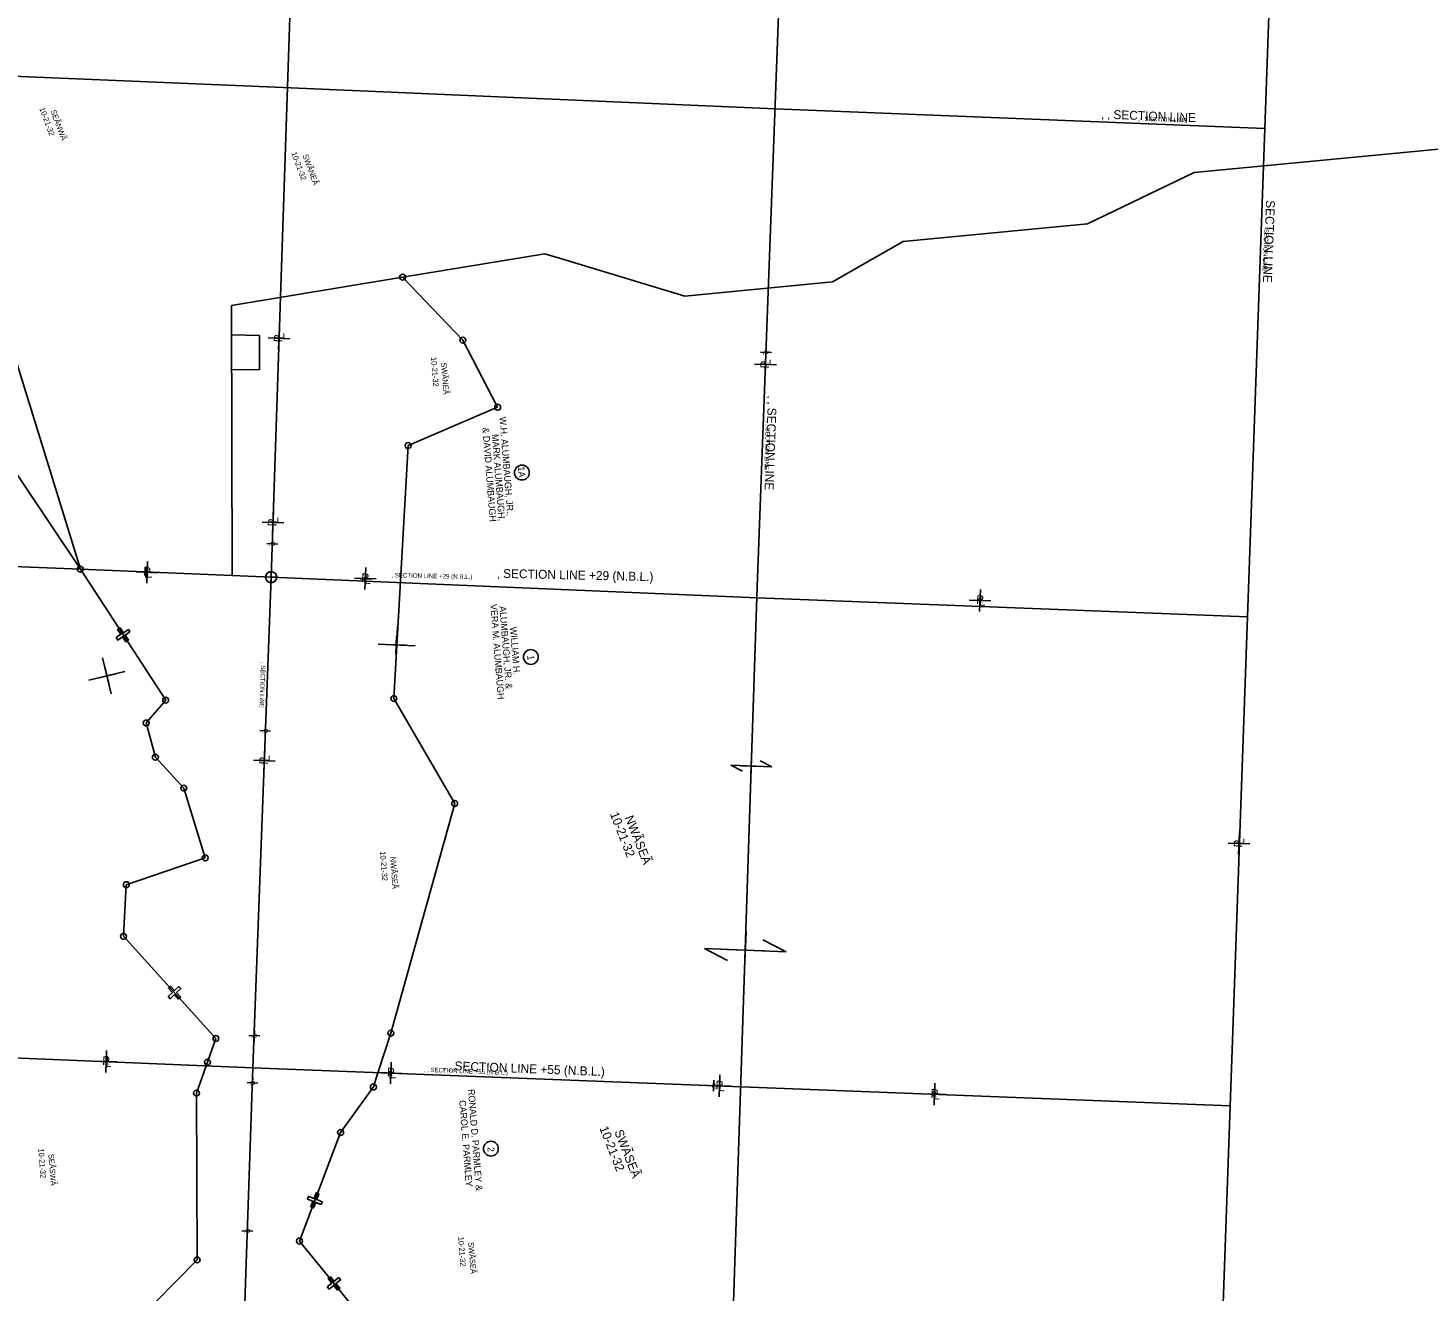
# Model space of a CAD drawing. Extents: x 2814293 to 2835768, y 121185 to 156337.
# Drawn here: x 2823143 to 2826922, y 142244 to 145654 of the extents above; entities that cross this region are included whole.
import ezdxf

# ---------------------------------------------------------------- set-up
doc = ezdxf.new("R2010")
doc.units = 0
for name, color, linetype in [('Default', 7, 'Continuous'), ('Photo-Retaining wall', 7, 'Continuous'), ('Roadway-Alignment notes', 7, 'Continuous'), ('Roadway-Ditches', 7, 'Continuous'), ('Roadway-Edge of pavement', 7, 'Continuous'), ('Roadway-Edge of shoulder', 7, 'Continuous'), ('Roadway-Entrances', 7, 'Continuous'), ('Roadway-New rw', 7, 'Continuous'), ('Roadway-Safety', 7, 'Continuous'), ('Roadway-Walls', 7, 'Continuous'), ('Scratch-2', 7, 'Continuous'), ('Scratch-4', 7, 'Continuous'), ('Scratch-5', 7, 'Continuous'), ('Text-New rw label', 7, 'Continuous'), ('Traffic_Control-Traffic barriers', 7, 'Continuous')]:
    doc.layers.add(name, color=color, linetype=linetype)

msp = doc.modelspace()

# ---------------------------------------------------------------- linework, layer by layer
at = {"layer": 'Default'}
for p, q in [((2824135.8, 143938), (2824140.5, 144037.9)), ((2824136.1, 143963), (2824137.9, 144013)), ((2824188.1, 143985.6), (2824088.2, 143990.3)), ((2824162, 143987.1), (2824112, 143988.9)), ((2823367.6, 143855.9), (2823344, 143953.1)), ((2823404.4, 143916.3), (2823307.2, 143892.7)), ((2823380.1, 143910.4), (2823331.5, 143898.6)), ((2823361.7, 143880.2), (2823349.9, 143928.8))]:
    msp.add_line(p, q, dxfattribs=at)
at = {"layer": 'Roadway-Ditches'}
for centre in [(2824476, 144453.5), (2824500.2, 143955.6), (2824392.4, 142628)]:
    msp.add_circle(centre, 20, dxfattribs=at)
at = {"layer": 'Roadway-Edge of pavement'}
for p, q in [((2825096.2, 143686.1), (2825094.3, 143636.2)), ((2825119.1, 143675), (2825150.2, 143659)), ((2825150.2, 143659), (2825040.3, 143663.3)), ((2825071.4, 143647.3), (2825040.3, 143663.3)), ((2825070.3, 143662.1), (2825120.2, 143660.2)), ((2825095.2, 143661.2), (2825095.2, 143661.2))]:
    msp.add_line(p, q, dxfattribs=at)
at = {"layer": 'Roadway-Edge of shoulder'}
for p, q in [((2823819.2, 144786.5), (2823821.5, 144845.4)), ((2823791, 144817.1), (2823849.8, 144814.8)), ((2825132.4, 144715.7), (2825134.5, 144774.6)), ((2825104, 144746.2), (2825162.9, 144744.1)), ((2823774.9, 144320), (2823833.8, 144317.7)), ((2823803.2, 144289.4), (2823805.5, 144348.3)), ((2823465.5, 144213.6), (2823463.3, 144154.7)), ((2823435, 144185.3), (2823493.8, 144183)), ((2824023.9, 144168.5), (2824082.8, 144166.2)), ((2824054.5, 144196.8), (2824052.2, 144137.9)), ((2825713.9, 144137.7), (2825711.6, 144078.8)), ((2825683.3, 144109.4), (2825742.2, 144107.1)), ((2823751.6, 143676.9), (2823810.5, 143674.6)), ((2823779.9, 143646.3), (2823782.2, 143705.2)), ((2826410.3, 143422.4), (2826412.6, 143481.3)), ((2826382, 143453), (2826440.9, 143450.7)), ((2823355.2, 142892.7), (2823352.9, 142833.8)), ((2823324.6, 142864.4), (2823383.5, 142862.1)), ((2824123.6, 142861.8), (2824121.3, 142802.9)), ((2824093, 142833.5), (2824151.8, 142831.2)), ((2825010.6, 142827), (2825008.3, 142768.1)), ((2825591, 142804.6), (2825588.7, 142745.7)), ((2824980, 142798.7), (2825038.9, 142796.4)), ((2825560.4, 142776.3), (2825619.3, 142774))]:
    msp.add_line(p, q, dxfattribs=at)
at = {"layer": 'Roadway-Entrances'}
for p, q in [((2825207.6, 146757.1), (2825111.4, 144144.8)), ((2823799.2, 144171.2), (2823859.8, 145995.8)), ((2826495.8, 145785.5), (2826434.8, 144063.6)), ((2821197.2, 145604), (2823831.6, 145493.6)), ((2823831.7, 145493.6), (2825159.5, 145435.9)), ((2825159.5, 145435.9), (2826481.5, 145382.7)), ((2821148.7, 144280.6), (2823284.2, 144192.5)), ((2823284.2, 144192.5), (2823693.6, 144175.6)), ((2823693.6, 144175.6), (2823799.2, 144171.2)), ((2823799.2, 144171.2), (2823750.1, 142846.6)), ((2825111.3, 144115.2), (2823799.2, 144171.2)), ((2825111.4, 144144.8), (2825022.5, 141475.7)), ((2826434.8, 144063.6), (2825111.3, 144115.2)), ((2826434.8, 144063.6), (2826341.2, 141424.5)), ((2821095.2, 142957.1), (2823750.2, 142846.3)), ((2823750.1, 142846.6), (2823703.8, 141527.1)), ((2823750.2, 142846.3), (2826388, 142744.1))]:
    msp.add_line(p, q, dxfattribs=at)
at = {"layer": 'Roadway-New rw'}
for p, q in [((2822908.4, 144755), (2823284.2, 144192.5)), ((2823284.2, 144192.5), (2823514.6, 143838.9)), ((2823514.6, 143838.9), (2823462.1, 143777.4)), ((2823462.1, 143777.4), (2823486.8, 143685)), ((2823486.8, 143685), (2823563.4, 143601.4)), ((2823563.4, 143601.4), (2823621.4, 143413.1)), ((2823621.4, 143413.1), (2823408.3, 143340.7)), ((2823408.3, 143340.7), (2823400.8, 143201.4)), ((2823400.8, 143201.4), (2823650.2, 142925.5)), ((2823650.2, 142925.5), (2823597.7, 142778)), ((2824075.2, 142794.7), (2824087.6, 142833.2)), ((2823597.7, 142778), (2823599.7, 142327.9)), ((2823986.7, 142671.5), (2824075.2, 142794.7)), ((2823875.8, 142378.6), (2823986.7, 142671.5)), ((2824046.6, 142168.9), (2823875.8, 142378.6)), ((2823599.7, 142327.9), (2823405.7, 142131.8))]:
    msp.add_line(p, q, dxfattribs=at)
for points in [[(2823380.6, 144007.9), (2823385, 144001.2), (2823398.3, 144010.1), (2823407.2, 143996.8), (2823413.9, 144001.3), (2823404.9, 144014.6), (2823418.2, 144023.5), (2823413.8, 144030.2), (2823400.5, 144021.2), (2823391.6, 144034.5), (2823384.9, 144030.1), (2823393.8, 144016.8), (2823380.6, 144007.9)], [(2823521, 143038.9), (2823526.5, 143033), (2823538.2, 143043.9), (2823549.1, 143032.1), (2823554.9, 143037.6), (2823544.1, 143049.3), (2823555.8, 143060.2), (2823550.4, 143066), (2823538.6, 143055.2), (2823527.8, 143066.9), (2823521.9, 143061.5), (2823532.8, 143049.7), (2823521, 143038.9)], [(2823906.3, 142471), (2823913.7, 142468.2), (2823919.5, 142483.1), (2823934.4, 142477.4), (2823937.3, 142484.8), (2823922.3, 142490.6), (2823928.1, 142505.5), (2823920.6, 142508.4), (2823914.9, 142493.4), (2823899.9, 142499.2), (2823897.1, 142491.7), (2823912, 142486), (2823906.3, 142471)], [(2823950.5, 142254.9), (2823955.5, 142248.7), (2823968, 142258.7), (2823978, 142246.2), (2823984.2, 142251.2), (2823974.2, 142263.7), (2823986.7, 142273.7), (2823981.7, 142279.9), (2823969.2, 142269.9), (2823959.2, 142282.4), (2823953, 142277.4), (2823963, 142264.9), (2823950.5, 142254.9)]]:
    msp.add_lwpolyline(points, close=True, dxfattribs=at)
at = {"layer": 'Roadway-Walls'}
for p, q in [((2825149.7, 144777.7), (2825120.3, 144778.7)), ((2825135.5, 144792.9), (2825134.5, 144763.5)), ((2823802.8, 144275.8), (2823801.6, 144246.4)), ((2823816.9, 144260.5), (2823787.5, 144261.7)), ((2823462.1, 144200), (2823461, 144170.5)), ((2823446.8, 144185.8), (2823476.3, 144184.7)), ((2824039.6, 144166.9), (2824069, 144165.7)), ((2824054.9, 144181), (2824053.8, 144151.6)), ((2825698.4, 144108.7), (2825727.9, 144107.6)), ((2825713.7, 144122.8), (2825712.6, 144093.4)), ((2823797.9, 143755.7), (2823768.5, 143756.8)), ((2823783.8, 143771), (2823782.7, 143741.5)), ((2823768.6, 142932.3), (2823739.1, 142933.4)), ((2823754.4, 142947.6), (2823753.3, 142918.1)), ((2823356.3, 142877.4), (2823355.2, 142847.9)), ((2823341, 142863.2), (2823370.5, 142862.1)), ((2824122.1, 142846.6), (2824120.9, 142817.2)), ((2823763.6, 142805.2), (2823734.2, 142806.4)), ((2823749.5, 142820.5), (2823748.4, 142791.1)), ((2824106.8, 142832.5), (2824136.2, 142831.4)), ((2824994.1, 142812.9), (2824992.9, 142783.5)), ((2824978.8, 142798.8), (2825008.2, 142797.6)), ((2825574.2, 142776), (2825603.6, 142774.9)), ((2825589.5, 142790.1), (2825588.4, 142760.7)), ((2823749.5, 142405.5), (2823720.1, 142406.6)), ((2823735.4, 142420.8), (2823734.2, 142391.3))]:
    msp.add_line(p, q, dxfattribs=at)
at = {"layer": 'Scratch-2'}
for p, q in [((2825081, 143213.8), (2825077.1, 143113.9)), ((2825126.7, 143191.6), (2825189, 143159.6)), ((2825189, 143159.6), (2824969.2, 143168.1)), ((2825031.4, 143136.1), (2824969.2, 143168.1)), ((2825029.1, 143165.8), (2825129, 143161.9)), ((2825079.1, 143163.8), (2825079.1, 143163.8))]:
    msp.add_line(p, q, dxfattribs=at)
at = {"layer": 'Scratch-4'}
for p, q in [((2823784.2, 144171.7), (2823799.2, 144171.2)), ((2823799.2, 144171.2), (2823798.7, 144156.2)), ((2823799.2, 144171.2), (2823799.7, 144186.2)), ((2823814.2, 144170.7), (2823799.2, 144171.2))]:
    msp.add_line(p, q, dxfattribs=at)
msp.add_circle((2823799.2, 144171.2), 15, dxfattribs=at)
for start, end in [(88.1, 178.1), (268.1, 358.1)]:
    msp.add_arc((2823799.2, 144171.2), 15, start, end, dxfattribs=at)
at = {"layer": 'Text-New rw label'}
for centre in [(2823284.2, 144192.5), (2823514.6, 143838.9), (2823462.1, 143777.4), (2823486.8, 143685), (2823563.4, 143601.4), (2823621.4, 143413.1), (2823408.3, 143340.7), (2823400.8, 143201.4), (2823650.2, 142925.5), (2823627.5, 142861.7), (2824075.2, 142794.7), (2823597.7, 142778), (2823986.7, 142671.5), (2823875.8, 142378.6), (2823599.7, 142327.9)]:
    msp.add_circle(centre, 8, dxfattribs=at)
at = {"layer": 'Traffic_Control-Traffic barriers'}
for p, q in [((2826290.6, 145263.5), (2827982.7, 145426.4)), ((2826002.5, 145125.2), (2826290.6, 145263.5)), ((2825504.8, 145077.3), (2826002.5, 145125.2)), ((2825314.3, 144968.5), (2825504.8, 145077.3)), ((2824154.1, 144981.1), (2824537.9, 145044.5)), ((2824537.9, 145044.5), (2824607.5, 145023.5)), ((2824607.5, 145023.5), (2824916.2, 144930.2)), ((2823692, 144904.9), (2824154.1, 144981.1)), ((2824154.1, 144981.1), (2824316.5, 144810.8)), ((2824916.2, 144930.2), (2825314.3, 144968.5)), ((2824316.5, 144810.8), (2824410.6, 144629.8)), ((2824410.6, 144629.8), (2824168.8, 144526.3)), ((2824168.8, 144526.3), (2824130.2, 143843.5)), ((2824130.2, 143843.5), (2824294.6, 143560.1)), ((2824294.6, 143560.1), (2824122.1, 142940)), ((2824087.6, 142833.2), (2824122.1, 142940))]:
    msp.add_line(p, q, dxfattribs=at)
for points in [[(2819850.1, 149939.6), (2820531.6, 149276.8), (2821431.4, 147698.1), (2821413.4, 147540.2), (2821396.7, 147393.2), (2821369.3, 147151.1), (2821340.3, 146896.2), (2821740.6, 145780.7), (2822160.2, 145252), (2822565.5, 145142.6), (2822781.5, 145084.2), (2823030.3, 145017.1), (2823072.5, 144880), (2823092.1, 144816.2), (2823284.2, 144192.5)], [(2823692, 144904.9), (2823693.6, 144175.6)], [(2823692.2, 144825), (2823767.5, 144823.8), (2823767.5, 144731.6), (2823692.4, 144730.6)]]:
    msp.add_lwpolyline(points, dxfattribs=at)
for centre in [(2824154.1, 144981.1), (2824316.5, 144810.8), (2824410.6, 144629.8), (2824168.8, 144526.3), (2824130.2, 143843.5), (2824294.6, 143560.1), (2824122.1, 142940)]:
    msp.add_circle(centre, 8, dxfattribs=at)

# ---------------------------------------------------------------- texts
at = {"layer": 'Photo-Retaining wall'}
for s, rotation, p in [('10-21-32', 290.3561, (2823173.4, 145436.4)), ('SEÃNWÃ', 290.3561, (2823203.5, 145429.9)), ('10-21-32', 290.3561, (2823853.5, 145316.1)), ('SWÃNEÃ', 290.3561, (2823883.7, 145309.6)), ('10-21-32', 274.4738, (2824230.5, 144764.9)), ('SWÃNEÃ', 274.4738, (2824257.7, 144750.4)), ('10-21-32', 274.4738, (2824092.9, 143430.2)), ('NWÃSEÃ', 274.4738, (2824120.1, 143415.7)), ('10-21-32', 274.4738, (2823170.6, 142627.8)), ('SEÃSWÃ', 274.4738, (2823197.8, 142613.3)), ('10-21-32', 274.4738, (2824303.7, 142389.7)), ('SWÃSEÃ', 274.4738, (2824331, 142375.2))]:
    msp.add_text(s, height=15, rotation=rotation, dxfattribs=at).set_placement(p)
at = {"layer": 'Roadway-Alignment notes'}
for s, p in [('10-21-32', (2824713.2, 143531.8)), ('NWÃSEÃ', (2824753.5, 143522.3)), ('10-21-32', (2824684.9, 142683.6)), ('SWÃSEÃ', (2824725.2, 142674.1))]:
    msp.add_text(s, height=24, rotation=291.4209, dxfattribs=at).set_placement(p)
at = {"layer": 'Roadway-Ditches'}
for s, p in [('W.H. ALUMBAUGH, JR.,', (2824415.3, 144603.6)), ('& DAVID ALUMBAUGH', (2824369.4, 144574.7)), ('MARK ALUMBAUGH,', (2824394.9, 144556.8)), ('1A', (2824465.3, 144469.4)), ('VERA M. ALUMBAUGH', (2824390.8, 144097.7)), ('ALUMBAUGH, JR. &', (2824415.2, 144092.4)), ('WILLIAM H.', (2824443.7, 144036.3)), ('1', (2824490.4, 143959.6)), ('RONALD D. PARMLEY &', (2824330.4, 142788.3)), ('CAROL E. PARMLEY', (2824306.7, 142758.1)), ('2', (2824383.1, 142631.9))]:
    msp.add_text(s, height=18, rotation=274.4738, dxfattribs=at).set_placement(p)
at = {"layer": 'Roadway-Edge of shoulder'}
for s, rotation, p in [('P', 87.7804, (2823829.6, 144804.9)), ('L', 87.7804, (2823834.2, 144812.7)), ('P', 87.9775, (2825142.7, 144734.1)), ('L', 87.9775, (2825147.3, 144742)), ('P', 87.7804, (2823813.5, 144307.8)), ('L', 87.7804, (2823818.1, 144315.6)), ('P', 357.7804, (2823453.4, 144174.9)), ('L', 357.7804, (2823461.2, 144170.3)), ('P', 357.7804, (2824042.3, 144158.2)), ('L', 357.7804, (2824050.1, 144153.5)), ('P', 357.7804, (2825701.7, 144099)), ('L', 357.7804, (2825709.5, 144094.4)), ('P', 87.7804, (2823790.3, 143664.7)), ('L', 87.7804, (2823794.9, 143672.5)), ('P', 87.7804, (2826420.7, 143440.8)), ('L', 87.7804, (2826425.3, 143448.7)), ('P', 357.7804, (2823343, 142854)), ('L', 357.7804, (2823350.8, 142849.4)), ('P', 357.7804, (2824111.4, 142823.1)), ('L', 357.7804, (2824119.2, 142818.5)), ('P', 357.7804, (2824998.4, 142788.4)), ('L', 357.7804, (2825006.3, 142783.7)), ('P', 357.7804, (2825578.8, 142765.9)), ('L', 357.7804, (2825586.6, 142761.3))]:
    msp.add_text(s, height=23.6, rotation=rotation, dxfattribs=at).set_placement(p)
at = {"layer": 'Roadway-Safety'}
for s, rotation, p in [('‚ ‚ SECTION LINE', 357.7804, (2826140, 145403.6)), ('SECTION LINE', 267.8429, (2826479.7, 145111.6)), ('‚ ‚ SECTION LINE', 267.9775, (2825134.7, 144592.2)), ('‚ SECTION LINE +29 (N.B.L.)', 358.7804, (2824124.4, 144170.7)), ('‚ SECTION LINE', 268.0989, (2823772, 143941.8)), ('‚ ‚ SECTION LINE +55 (N.B.L.)', 357.7804, (2824212.2, 142835.7))]:
    msp.add_text(s, height=12, rotation=rotation, dxfattribs=at).set_placement(p)
at = {"layer": 'Roadway-Walls'}
for s, rotation, p in [('L', 267.9775, (2825128.1, 144779.8)), ('P', 267.9775, (2825130.4, 144783.7)), ('L', 267.7804, (2823795.3, 144262.7)), ('P', 267.7804, (2823797.6, 144266.6)), ('P', 357.7804, (2823456, 144180.7)), ('L', 357.7804, (2823459.9, 144178.4)), ('P', 357.7804, (2824048.8, 144161.7)), ('L', 357.7804, (2824052.7, 144159.4)), ('P', 357.7804, (2825707.6, 144103.5)), ('L', 357.7804, (2825711.5, 144101.2)), ('L', 267.7804, (2823776.3, 143757.9)), ('P', 267.7804, (2823778.6, 143761.8)), ('L', 267.7804, (2823746.9, 142934.5)), ('P', 267.7804, (2823749.2, 142938.4)), ('P', 357.7804, (2823350.2, 142858)), ('L', 357.7804, (2823354.1, 142855.7)), ('P', 357.7804, (2824116, 142827.3)), ('L', 267.7804, (2823742, 142807.4)), ('P', 267.7804, (2823744.3, 142811.3)), ('L', 357.7804, (2824119.9, 142825)), ('P', 357.7804, (2824988, 142793.6)), ('L', 357.7804, (2824991.9, 142791.3)), ('P', 357.7804, (2825583.4, 142770.8)), ('L', 357.7804, (2825587.3, 142768.5)), ('L', 267.7804, (2823727.9, 142407.6)), ('P', 267.7804, (2823730.2, 142411.6))]:
    msp.add_text(s, height=11.8, rotation=rotation, dxfattribs=at).set_placement(p)
at = {"layer": 'Scratch-5'}
for s, rotation, p in [('‚ ‚ SECTION LINE', 357.7804, (2826040.1, 145409.5)), ('SECTION LINE', 267.8429, (2826484.7, 145189.2)), ('‚ ‚ SECTION LINE', 267.9775, (2825140.2, 144661)), ('‚ SECTION LINE +29 (N.B.L.)', 358.7804, (2824409, 144169.4)), ('‚ ‚ SECTION LINE +55 (N.B.L.)', 357.7804, (2824261.8, 142841))]:
    msp.add_text(s, height=24, rotation=rotation, dxfattribs=at).set_placement(p)

doc.saveas('drawing.dxf')
